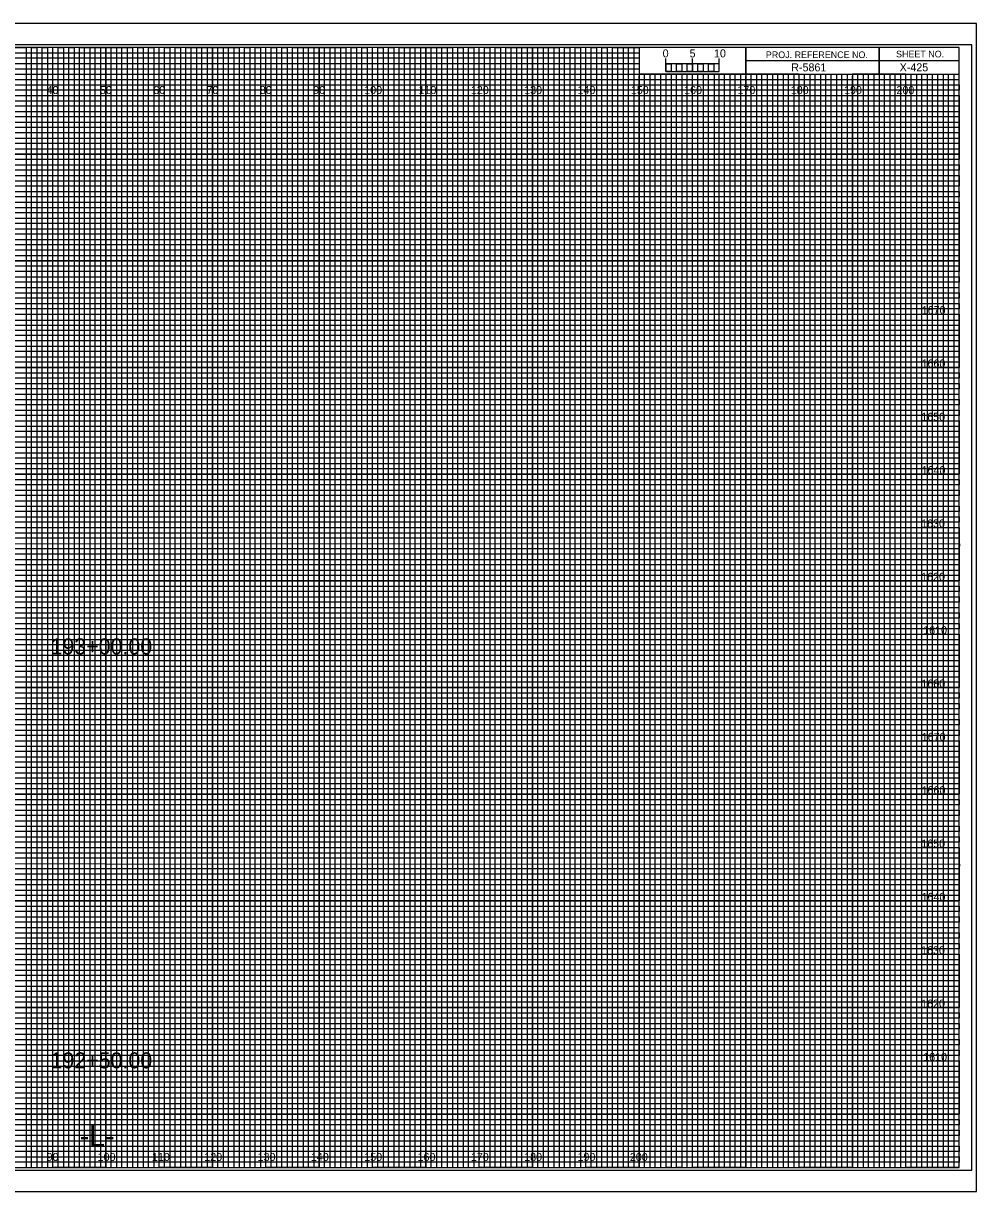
# Model space of a CAD drawing. Extents: x -13 to 323, y -5 to 6154.
# Drawn here: x 144.5 to 323.3, y 4615.5 to 4834.5 of the extents above; entities that cross this region are included whole.
import ezdxf

# ---------------------------------------------------------------- set-up
doc = ezdxf.new("R2010")
doc.units = 0
for name, color, linetype in [('Exist CMT Ground Line', 7, 'Continuous'), ('Prop Horizontal Alignment', 7, 'Continuous'), ('Prop Retaining Wall', 7, 'Continuous'), ('Prop XS Alignment Label', 7, 'Continuous'), ('Prop XS Bar Scale Labels', 7, 'Continuous'), ('Prop XS DDE', 7, 'Continuous'), ('Prop XS DDE Elevations', 7, 'Continuous'), ('Prop XS DDE Slope Text', 7, 'Continuous'), ('Prop XS Earthwork Shape', 7, 'Continuous'), ('Prop XS Elevation Labels', 7, 'Continuous'), ('Prop XS Project Number', 7, 'Continuous'), ('Prop XS Sheet Number', 7, 'Continuous'), ('Prop XS Station Labels', 7, 'Continuous'), ('Raster_Level_0', 7, 'Continuous'), ('Scratch_Level_3', 7, 'Continuous'), ('Sheet Cutting Line CELL', 7, 'Continuous')]:
    doc.layers.add(name, color=color, linetype=linetype)

msp = doc.modelspace()

# ---------------------------------------------------------------- linework, layer by layer
at = {"layer": 'Exist CMT Ground Line'}
for p, q in [((265, 4825.49), (265, 4827.9)), ((265, 4826.9), (265, 4827.9)), ((270, 4825.49), (270, 4827.9)), ((275, 4825.49), (275, 4827.9)), ((275, 4826.9), (275, 4827.9))]:
    msp.add_line(p, q, dxfattribs=at)
for points in [[(275, 4826.9), (265, 4826.9), (265, 4825.49), (275, 4825.49)], [(265, 4826.9), (266, 4826.9), (266, 4825.49), (265, 4825.49)], [(267, 4826.9), (268, 4826.9), (268, 4825.49), (267, 4825.49)], [(269, 4826.9), (270, 4826.9), (270, 4825.49), (269, 4825.49)], [(271, 4826.9), (272, 4826.9), (272, 4825.49), (271, 4825.49)], [(273, 4826.9), (274, 4826.9), (274, 4825.49), (273, 4825.49)]]:
    msp.add_lwpolyline(points, close=True, dxfattribs=at)
at = {"layer": 'Prop Retaining Wall'}
for p, q in [((0, 4829), (260, 4829)), ((260, 4829), (260, 4827.98)), ((260, 4827.98), (0, 4827.98)), ((0, 4827), (260, 4827)), ((260, 4827), (260, 4825.89)), ((260, 4825.89), (0, 4825.89)), ((0, 4824), (320, 4824))]:
    msp.add_line(p, q, dxfattribs=at)
for points in [[(0, 4823), (270, 4823), (320, 4823), (320, 4822), (0, 4822)], [(0, 4821), (320, 4821), (320, 4819), (0, 4819)], [(0, 4818), (320, 4818), (320, 4817), (0, 4816.98)], [(0, 4816), (320, 4816), (320, 4814), (0, 4814)], [(0, 4813), (320, 4813), (320, 4812), (0, 4812)], [(0, 4811), (320, 4811), (320, 4809), (0, 4809)], [(0, 4808), (320, 4808), (320, 4807), (0, 4807)], [(0, 4806), (320, 4806), (320, 4804), (0, 4804)], [(0, 4803), (320, 4803), (320, 4802), (0, 4802)], [(0, 4801), (320, 4801), (320, 4799), (0, 4799)], [(0, 4798), (320, 4798), (320, 4797), (0, 4797)], [(0, 4796), (320, 4796), (320, 4793.95), (320, 4793), (320, 4792), (0, 4792)], [(0, 4794), (320, 4794), (320, 4793), (0, 4793)], [(0, 4791), (320, 4791), (320, 4789), (0, 4789.03)], [(0, 4789.03), (320, 4789), (320, 4788), (0, 4788)], [(0, 4787), (320, 4787), (320, 4786), (0, 4786)], [(0, 4784), (320, 4784), (320, 4783), (0, 4783)], [(0, 4782), (320, 4782), (320, 4781), (0, 4781)], [(-0.07, 4778.89), (320, 4778.89), (320, 4777.88), (-0.07, 4777.88)], [(0, 4777), (320, 4777), (320, 4776), (0, 4776)], [(0, 4774), (320, 4774), (320, 4773), (0, 4773)], [(0, 4772), (320, 4772), (320, 4771), (0, 4771)], [(0, 4769), (320, 4769), (320, 4768), (0, 4768)], [(0, 4767), (320, 4767), (320, 4766), (0, 4766)], [(0, 4764), (320, 4764), (320, 4763), (0, 4763)], [(0, 4762), (320, 4762), (320, 4761), (0, 4761)], [(0, 4759), (320, 4759), (319.99, 4757.98), (0, 4758)], [(0, 4757), (320, 4757), (320, 4756), (0, 4756)], [(0, 4754), (320, 4754), (320, 4753), (0, 4753)], [(0, 4752), (320, 4752), (320, 4751), (0, 4751)], [(0, 4749), (320, 4749), (320, 4748), (0, 4748)], [(0, 4747), (320, 4747), (320, 4746), (0, 4746)], [(0, 4744), (320, 4744), (320, 4743), (0, 4743)], [(0, 4742), (320, 4742), (320, 4741), (0, 4741)], [(0, 4739), (320, 4739), (320, 4738), (0, 4738)], [(0, 4736.99), (320.07, 4736.91), (320, 4736), (0, 4736)], [(0, 4734), (320, 4734), (320, 4733), (0, 4733)], [(0, 4732), (320, 4732), (320, 4731), (0, 4731)], [(0, 4729), (320, 4729), (320, 4728), (0, 4728)], [(0, 4727), (320, 4727), (320, 4726), (0, 4726)], [(0, 4724), (320, 4724), (320, 4723), (0, 4723)], [(0, 4722), (320, 4722), (320, 4721), (0, 4721)], [(0, 4719), (320, 4719), (320, 4718), (0, 4718)], [(0, 4717), (320, 4717), (320, 4716), (0, 4716)], [(0, 4714), (320, 4714), (320, 4713), (0, 4713)], [(0, 4712), (320, 4712), (320, 4711), (0, 4711)], [(0, 4709), (320, 4709), (320, 4708), (0, 4708)], [(0, 4707), (320, 4707), (320, 4706), (0, 4706)], [(0, 4704), (320, 4704), (320, 4703), (0, 4703)], [(0, 4702), (320, 4702), (320, 4701), (0, 4701)], [(0, 4699), (320, 4699), (319.99, 4697.98), (0, 4698)], [(0, 4697), (320, 4697), (320, 4696), (0, 4696)], [(0, 4694), (320, 4694), (320, 4693), (0, 4693)], [(0, 4692), (320, 4692), (320, 4691), (0, 4691)], [(0, 4689), (320, 4689), (320, 4688), (0, 4688)], [(0, 4687), (320, 4687), (320, 4686), (0, 4686)], [(0, 4684), (320, 4684), (320, 4683), (0, 4683)], [(0, 4682), (320, 4682), (320, 4681), (0, 4681)], [(0, 4679), (320, 4679), (320, 4678), (0, 4678)], [(0, 4676.99), (320.07, 4676.91), (320, 4676), (0, 4676)], [(0, 4674), (320, 4674), (320, 4673), (0, 4673)], [(0, 4672), (320, 4672), (320, 4671), (0, 4671)], [(0, 4669), (320, 4669), (320, 4668), (0, 4668)], [(0, 4667), (320, 4667), (320, 4666), (0, 4666)], [(0, 4664), (320, 4664), (320, 4663), (0, 4663)], [(0, 4662), (320, 4662), (320, 4661), (0, 4661)], [(0, 4659), (320, 4659), (320, 4658), (0, 4658)], [(0, 4657), (320, 4657), (320, 4656), (0, 4656)], [(0, 4654), (320, 4654), (320, 4653), (0, 4653)], [(0, 4652), (320, 4652), (320, 4651), (0, 4651)], [(0, 4649), (320, 4649), (320, 4648), (0, 4648)], [(0, 4647), (320, 4647), (320, 4646), (0, 4646)], [(0, 4644), (320, 4644), (320, 4643), (0, 4643)], [(0, 4642), (320, 4642), (320, 4641), (0, 4641)], [(0, 4639), (320, 4639), (320, 4638), (0, 4638)], [(0, 4637), (320, 4637), (320, 4636), (0, 4636)], [(0, 4634), (320, 4634), (320, 4633), (0, 4633)], [(0, 4632), (320, 4632), (320, 4631), (0, 4631)], [(0, 4629), (320, 4629), (320, 4628), (0, 4628)], [(0, 4627), (320, 4627), (320, 4626), (0, 4626)], [(0, 4624), (320, 4624), (320, 4623), (0, 4623)], [(0, 4622), (320, 4622), (320, 4621), (0, 4621)]]:
    msp.add_lwpolyline(points, dxfattribs=at)
at = {"layer": 'Prop XS Alignment Label'}
for p, q in [((305, 4830), (305, 4825)), ((305, 4825), (305, 4830)), ((280, 4827.5), (280, 4825)), ((320, 4827.49), (280, 4827.49)), ((280, 4825), (320, 4825))]:
    msp.add_line(p, q, dxfattribs=at)
for points in [[(320, 4830), (0, 4830), (0, 4620), (320, 4620)], [(280, 4830), (260, 4830), (260, 4825.03), (280, 4825.03)], [(320, 4830), (280, 4830), (280, 4825), (320, 4825)]]:
    msp.add_lwpolyline(points, close=True, dxfattribs=at)
at = {"layer": 'Prop XS DDE'}
msp.add_lwpolyline([(-13.4, 4615.5), (323.3, 4615.5), (323.3, 4834.5), (-13.4, 4834.5)], close=True, dxfattribs=at)
at = {"layer": 'Prop XS DDE Elevations'}
for p, q in [((150, 4620), (150, 4830)), ((160, 4620), (160, 4830)), ((170, 4620), (170, 4830)), ((180, 4620), (180, 4830)), ((190, 4620), (190, 4830)), ((200, 4620), (200, 4830)), ((210, 4620), (210, 4830)), ((220, 4620), (220, 4830)), ((230, 4620), (230, 4830)), ((240, 4620), (240, 4830)), ((250, 4620), (250, 4830)), ((260, 4620), (260, 4824.69)), ((270, 4620), (270, 4824.69)), ((280, 4620), (280, 4824.69)), ((290, 4620), (290, 4824.69)), ((300, 4620), (300, 4824.69)), ((310, 4620), (310, 4824.69)), ((0, 4820), (320, 4820)), ((0, 4810), (320, 4810)), ((0, 4800), (320, 4800)), ((0, 4790), (320, 4790)), ((0, 4780), (320, 4780)), ((0, 4770), (320, 4770)), ((0, 4760), (320, 4760)), ((0, 4750), (320, 4750)), ((0, 4740), (320, 4740)), ((0, 4730), (320, 4730)), ((0, 4720), (320, 4720)), ((0, 4710), (320, 4710)), ((0, 4700), (320, 4700)), ((0, 4690), (320, 4690)), ((0, 4680), (320, 4680)), ((0, 4670), (320, 4670)), ((0, 4660), (320, 4660)), ((0, 4650), (320, 4650)), ((0, 4640), (320, 4640)), ((0, 4630), (320, 4630))]:
    msp.add_line(p, q, dxfattribs=at)
at = {"layer": 'Prop XS DDE Slope Text'}
msp.add_lwpolyline([(-10.8, 4619.5), (322.4, 4619.5), (322.4, 4830.5), (-10.8, 4830.5)], close=True, dxfattribs=at)
at = {"layer": 'Prop XS Earthwork Shape'}
for p, q in [((150, 4830), (140, 4830)), ((150, 4620), (150, 4830)), ((170, 4830), (160, 4830)), ((160, 4830), (160, 4620)), ((170, 4620), (170, 4830)), ((190, 4830), (180, 4830)), ((180, 4830), (180, 4620)), ((190, 4620), (190, 4830)), ((210, 4830), (200, 4830)), ((200, 4830), (200, 4620)), ((210, 4620), (210, 4830)), ((230, 4830), (220, 4830)), ((220, 4830), (220, 4620)), ((230, 4620), (230, 4830)), ((250, 4830), (240, 4830)), ((240, 4830), (240, 4620)), ((250, 4620), (250, 4830)), ((260, 4830), (260, 4620)), ((270, 4620), (270, 4825)), ((290, 4825), (280, 4825)), ((280, 4825), (280, 4620)), ((290, 4620), (290, 4825)), ((310, 4825), (300, 4825)), ((300, 4825), (300, 4620)), ((310, 4620), (310, 4825)), ((160, 4620), (150, 4620)), ((180, 4620), (170, 4620)), ((200, 4620), (190, 4620)), ((220, 4620), (210, 4620)), ((240, 4620), (230, 4620)), ((260, 4620), (250, 4620)), ((280, 4620), (270, 4620)), ((300, 4620), (290, 4620)), ((320, 4620), (310, 4620)), ((320, 4620), (320, 4620))]:
    msp.add_line(p, q, dxfattribs=at)
for points in [[(0, 4820), (320, 4820), (320, 4810), (0, 4810)], [(0, 4800), (320, 4800), (320, 4790), (0, 4790)], [(0, 4780), (320, 4780), (320, 4770), (0, 4770)], [(0, 4760), (320, 4760), (320, 4750), (0, 4750)], [(0, 4740), (320, 4740), (320, 4730), (0, 4730)], [(0, 4720), (320, 4720), (320, 4710), (0, 4710)], [(0, 4700), (320, 4700), (320, 4690), (0, 4690)], [(0, 4680), (320, 4680), (320, 4670), (0, 4670)], [(0, 4660), (320, 4660), (320, 4650), (0, 4650)], [(0, 4640), (320, 4640), (320, 4630), (0, 4630)]]:
    msp.add_lwpolyline(points, dxfattribs=at)
at = {"layer": 'Prop XS Elevation Labels'}
for p, q in [((267, 4825), (266.01, 4825)), ((266.01, 4825), (266.01, 4620)), ((267, 4620), (267, 4825)), ((269, 4825), (268, 4825)), ((268, 4825), (268, 4620)), ((269, 4620), (269, 4825)), ((266.01, 4620), (265, 4620)), ((268, 4620), (267, 4620))]:
    msp.add_line(p, q, dxfattribs=at)
for points in [[(145, 4620), (146, 4620), (146, 4830), (147, 4830), (147, 4620)], [(147, 4620), (148, 4620), (148, 4830), (149, 4830), (149, 4620)], [(150, 4620), (151, 4620), (151, 4830), (152, 4830), (152, 4620)], [(152, 4620), (153, 4620), (153, 4830), (154, 4830), (154, 4620)], [(155, 4620), (156, 4620), (156, 4830), (157, 4830), (157, 4620)], [(157, 4620), (158, 4620), (158, 4830), (159, 4830), (159, 4620)], [(160, 4620), (161, 4620), (161, 4830), (162, 4830), (162, 4620)], [(162, 4620), (163, 4620), (163, 4830), (164, 4830), (164, 4620)], [(165, 4620), (166, 4620), (166, 4830), (167, 4830), (167, 4620)], [(167, 4620), (168, 4620), (168, 4830), (169, 4830), (169, 4620)], [(170, 4620), (171, 4620), (171, 4830), (172, 4830), (172, 4620)], [(172, 4620), (173, 4620), (173, 4830), (174, 4830), (174, 4620)], [(175, 4620), (176, 4620), (176, 4830), (177, 4830), (177, 4620)], [(177, 4620), (178, 4620), (178, 4830), (179, 4830), (179, 4620)], [(180, 4620), (181, 4620), (181, 4830), (182, 4830), (182, 4620)], [(182, 4620), (183, 4620), (183, 4830), (184, 4830), (184, 4620)], [(185, 4620), (186, 4620), (186, 4830), (187, 4830), (187, 4620)], [(187, 4620), (188, 4620), (188, 4830), (189, 4830), (189, 4620)], [(190, 4620), (191, 4620), (191, 4830), (192, 4830), (192, 4620)], [(192, 4620), (193, 4620), (193, 4830), (194, 4830), (194, 4620)], [(195, 4620), (196, 4620), (196, 4830), (197, 4830), (197, 4620)], [(197, 4620), (198, 4620), (198, 4830), (199, 4830), (199, 4620)], [(200, 4620), (201, 4620), (201, 4830), (202, 4830), (202, 4620)], [(202, 4620), (203, 4620), (203, 4830), (204, 4830), (204, 4620)], [(205, 4620), (206, 4620), (206, 4830), (207, 4830), (207, 4620)], [(207, 4620), (208, 4620), (208, 4830), (209, 4830), (209, 4620)], [(210, 4620), (211, 4620), (211, 4830), (212, 4830), (212, 4620)], [(212, 4620), (213, 4620), (213, 4830), (214, 4830), (214, 4620)], [(215, 4620), (216, 4620), (216, 4830), (217, 4830), (217, 4620)], [(217, 4620), (218, 4620), (218, 4830), (219, 4830), (219, 4620)], [(220, 4620), (221, 4620), (221, 4830), (222, 4830), (222, 4620)], [(222, 4620), (223, 4620), (223, 4830), (224, 4830), (224, 4620)], [(225, 4620), (226, 4620), (226, 4830), (227, 4830), (227, 4620)], [(227, 4620), (228, 4620), (228, 4830), (229, 4830), (229, 4620)], [(230, 4620), (231, 4620), (231, 4830), (232, 4830), (232, 4620)], [(232, 4620), (233, 4620), (233, 4830), (234, 4830), (234, 4620)], [(235, 4620), (236, 4620), (236, 4830), (237, 4830), (237, 4620)], [(237, 4620), (238, 4620), (238, 4830), (239, 4830), (239, 4620)], [(240, 4620), (241, 4620), (241, 4830), (242, 4830), (242, 4620)], [(242, 4620), (243, 4620), (243, 4830), (244, 4830), (244, 4620)], [(245, 4620), (246, 4620), (246, 4830), (247, 4830), (247, 4620)], [(247, 4620), (248, 4620), (248, 4830), (249, 4830), (249, 4620)], [(250, 4620), (251, 4620), (251, 4830), (252, 4830), (252, 4620)], [(252, 4620), (253, 4620), (253, 4830), (254, 4830), (254, 4620)], [(255, 4620), (256, 4620), (256, 4830), (257, 4830), (257, 4620)], [(257, 4620), (258, 4620), (258, 4830), (259, 4830), (259, 4620)], [(260, 4620), (261, 4620), (261, 4825), (262.02, 4825), (262.02, 4620)], [(262, 4620), (263, 4620), (263, 4825), (263.99, 4825), (263.99, 4620)], [(270, 4620), (270.98, 4620), (270.98, 4825), (272, 4825), (272, 4620)], [(272, 4620), (273, 4620), (273, 4825), (274.05, 4825), (274.05, 4620)], [(275, 4620), (276, 4620), (276, 4825), (277, 4825), (277, 4620)], [(277, 4620), (278, 4620), (278, 4825), (279, 4825), (279, 4620)], [(280, 4620), (281, 4620), (281, 4825), (282, 4825), (282, 4620)], [(282, 4620), (283, 4620), (283, 4825), (284, 4825), (284, 4620)], [(285, 4620), (286, 4620), (286, 4825), (287, 4825), (287, 4620)], [(287, 4620), (288, 4620), (288, 4825), (289, 4825), (289, 4620)], [(290, 4620), (291, 4620), (291, 4825), (292, 4825), (292, 4620)], [(292, 4620), (293, 4620), (293, 4825), (294, 4825), (294, 4620)], [(295, 4620), (296, 4620), (296, 4825), (297, 4825), (297, 4620)], [(297, 4620), (298, 4620), (298, 4825), (299, 4825), (299, 4620)], [(300, 4620), (301, 4620), (301, 4825), (302, 4825), (302, 4620)], [(302, 4620), (303, 4620), (303, 4825), (304, 4825), (304, 4620)], [(305, 4620), (306, 4620), (306, 4825), (307, 4825), (307, 4620)], [(307, 4620), (308, 4620), (308, 4825), (309, 4825), (309, 4620)], [(310, 4620), (311, 4620), (311, 4825), (312, 4825), (312, 4620)], [(312, 4620), (313, 4620), (313, 4825), (314, 4825), (314, 4620)], [(315, 4620), (316, 4620), (316, 4825), (317, 4825), (317, 4620)], [(317, 4620), (318, 4620), (318, 4825), (319, 4825), (319, 4620)]]:
    msp.add_lwpolyline(points, dxfattribs=at)
at = {"layer": 'Prop XS Station Labels'}
for points in [[(135, 4830), (145, 4830), (145, 4620), (155, 4620), (155, 4830), (165, 4830), (165, 4620), (175, 4620), (175, 4830), (185, 4830), (185, 4620), (195, 4620), (195, 4830), (205, 4830), (205, 4620), (215, 4620), (215, 4830), (225, 4830), (225, 4620), (235, 4620), (235, 4830), (245, 4830), (245, 4620), (255, 4620), (255, 4830), (259.93, 4830), (260, 4830), (260, 4825), (264.99, 4825), (264.99, 4620), (275, 4620), (275, 4825), (285, 4825), (285, 4620), (295, 4620), (295, 4825), (305, 4825), (305, 4620), (315, 4620), (315, 4825)], [(0, 4825), (275, 4825)], [(0, 4805), (320, 4805), (320, 4815), (0, 4815)], [(0, 4785), (320, 4785), (320, 4795), (0, 4795)], [(0, 4765), (320, 4765), (320, 4775), (0, 4775)], [(0, 4745), (320, 4745), (320, 4755), (0, 4755)], [(0, 4725), (320, 4725), (320, 4735), (0, 4735)], [(0, 4705), (320, 4705), (320, 4715), (0, 4715)], [(0, 4685), (320, 4685), (320, 4695), (0, 4695)], [(0, 4665), (320, 4665), (320, 4675), (0, 4675)], [(0, 4645), (320, 4645), (320, 4655), (0, 4655)], [(0, 4625), (320, 4625), (320, 4635), (0, 4635)]]:
    msp.add_lwpolyline(points, dxfattribs=at)
at = {"layer": 'Sheet Cutting Line CELL'}
for p, q in [((323.3, 4834.5), (-13.4, 4834.5)), ((-13.4, 4615.5), (323.3, 4615.5))]:
    msp.add_line(p, q, dxfattribs=at)

# ---------------------------------------------------------------- texts
at = {"layer": 'Exist CMT Ground Line'}
msp.add_text('0', height=1.5, dxfattribs=at).set_placement((264.41, 4828.12))
at = {"layer": 'Prop Horizontal Alignment'}
for s, p in [('193+00.00', (149.59, 4716.21)), ('192+50.00', (149.59, 4638.61))]:
    msp.add_text(s, height=3, dxfattribs=at).set_placement(p)
at = {"layer": 'Prop XS Alignment Label'}
for s, height, p in [('PROJ. REFERENCE NO.', 1.25, (283.77, 4827.99)), ('SHEET NO.', 1.25, (308.19, 4828.12)), ('-L-', 4, (155.06, 4624))]:
    msp.add_text(s, height=height, dxfattribs=at).set_placement(p)
at = {"layer": 'Prop XS Bar Scale Labels'}
for s, p in [('5', (269.47, 4828.12)), ('10', (274.04, 4828.12))]:
    msp.add_text(s, height=1.5, dxfattribs=at).set_placement(p)
at = {"layer": 'Prop XS Project Number'}
msp.add_text('R-5861', height=1.5, dxfattribs=at).set_placement((288.53, 4825.5))
at = {"layer": 'Prop XS Sheet Number'}
msp.add_text('X-425', height=1.5, dxfattribs=at).set_placement((308.86, 4825.51))
at = {"layer": 'Raster_Level_0'}
for s, p in [('40', (148.86, 4821.25)), ('50', (158.86, 4821.25)), ('60', (168.86, 4821.25)), ('70', (178.86, 4821.25)), ('80', (188.86, 4821.25)), ('90', (198.86, 4821.25)), ('100', (208.44, 4821.25)), ('110', (218.62, 4821.25)), ('120', (228.44, 4821.25)), ('130', (238.44, 4821.25)), ('140', (248.44, 4821.25)), ('150', (258.44, 4821.25)), ('160', (268.44, 4821.25)), ('170', (278.44, 4821.25)), ('180', (288.44, 4821.25)), ('190', (298.44, 4821.25)), ('200', (308.26, 4821.25)), ('90', (148.86, 4621.25)), ('100', (158.44, 4621.25)), ('110', (168.62, 4621.25)), ('120', (178.44, 4621.25)), ('130', (188.44, 4621.25)), ('140', (198.44, 4621.25)), ('150', (208.44, 4621.25)), ('160', (218.44, 4621.25)), ('170', (228.44, 4621.25)), ('180', (238.44, 4621.25)), ('190', (248.44, 4621.25)), ('200', (258.26, 4621.25))]:
    msp.add_text(s, height=1.5, dxfattribs=at).set_placement(p)
at = {"layer": 'Scratch_Level_3'}
for s, p in [('1670', (313, 4780)), ('1660', (312.97, 4770)), ('1650', (312.92, 4760)), ('1640', (312.97, 4750)), ('1630', (312.89, 4740)), ('1620', (312.9, 4730)), ('1610', (313.28, 4720)), ('1680', (312.95, 4710)), ('1600', (312.95, 4710)), ('1670', (313, 4700)), ('1660', (312.97, 4690)), ('1650', (312.92, 4680)), ('1640', (312.97, 4670)), ('1630', (312.89, 4660)), ('1620', (312.9, 4650)), ('1610', (313.28, 4640))]:
    msp.add_text(s, height=1.5, dxfattribs=at).set_placement(p)

doc.saveas('drawing.dxf')
